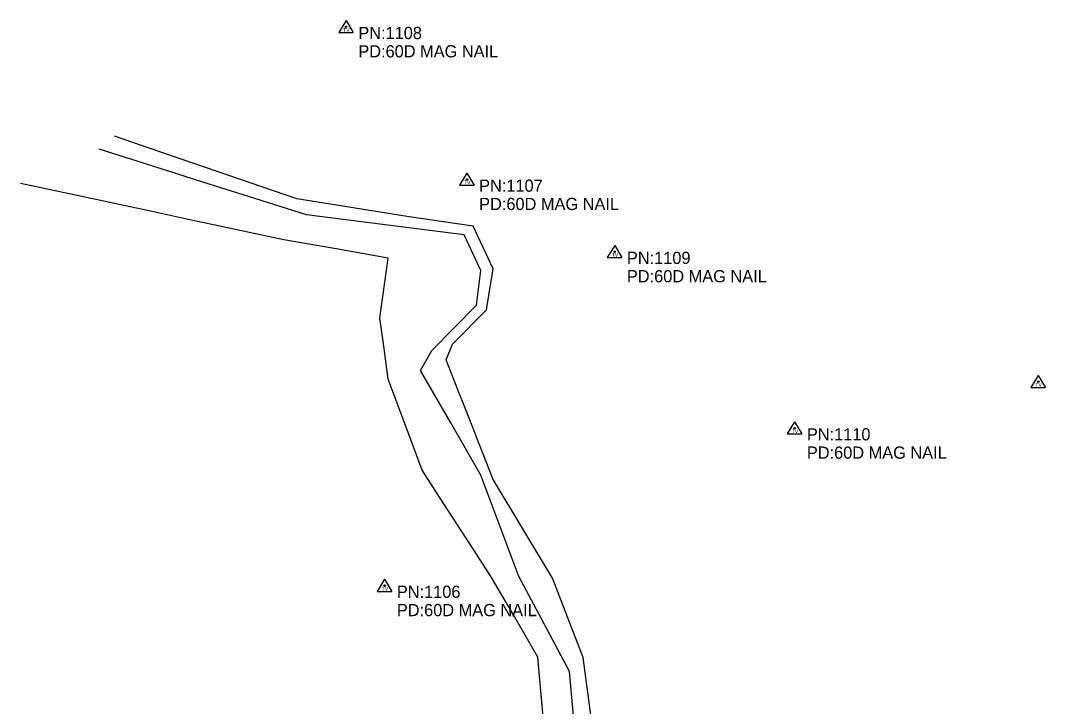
# Model space of a CAD drawing. Extents: x 1568433 to 1572450, y 731863 to 733450.
# Drawn here: x 1570330.9 to 1570750.2, y 732343.4 to 732624.2 of the extents above; entities that cross this region are included whole.
import ezdxf

# ---------------------------------------------------------------- set-up
doc = ezdxf.new("R2010")
doc.units = 0
for name, color, linetype in [('S_SECONDARY_CTL', 7, 'Continuous'), ('S_SECONDARY_CTL_ANNOT', 7, 'Continuous'), ('S_STREAM', 7, 'Continuous')]:
    doc.layers.add(name, color=color, linetype=linetype)

msp = doc.modelspace()

# ---------------------------------------------------------------- linework, layer by layer
at = {"layer": 'S_SECONDARY_CTL'}
for p, q in [((1570464.12, 732624.24), (1570461.11, 732619.28)), ((1570464.12, 732624.24), (1570467.06, 732619.28)), ((1570461.11, 732619.28), (1570467.06, 732619.28)), ((1570513.54, 732561.75), (1570510.53, 732556.79)), ((1570513.54, 732561.75), (1570516.49, 732556.79)), ((1570510.53, 732556.79), (1570516.49, 732556.79)), ((1570573.99, 732532.17), (1570570.98, 732527.22)), ((1570573.99, 732532.17), (1570576.94, 732527.22)), ((1570570.98, 732527.22), (1570576.94, 732527.22)), ((1570747.28, 732478.97), (1570744.27, 732474.02)), ((1570747.28, 732478.97), (1570750.23, 732474.02)), ((1570744.27, 732474.02), (1570750.23, 732474.02)), ((1570647.61, 732459.96), (1570644.6, 732455.01)), ((1570647.61, 732459.96), (1570650.56, 732455.01)), ((1570644.6, 732455.01), (1570650.56, 732455.01)), ((1570479.88, 732395.5), (1570476.87, 732390.54)), ((1570479.88, 732395.5), (1570482.83, 732390.54)), ((1570476.87, 732390.54), (1570482.83, 732390.54))]:
    msp.add_line(p, q, dxfattribs=at)
for centre, radius in [((1570464.12, 732621.63), 0.311), ((1570464.12, 732621.63), 0.183), ((1570464.12, 732621.63), 0.103), ((1570513.54, 732559.14), 0.311), ((1570513.54, 732559.14), 0.183), ((1570513.54, 732559.14), 0.103), ((1570573.99, 732529.56), 0.311), ((1570573.99, 732529.56), 0.183), ((1570573.99, 732529.56), 0.103), ((1570747.28, 732476.36), 0.311), ((1570747.28, 732476.36), 0.183), ((1570747.28, 732476.36), 0.103), ((1570647.61, 732457.35), 0.311), ((1570647.61, 732457.35), 0.183), ((1570647.61, 732457.35), 0.103), ((1570479.88, 732392.88), 0.311), ((1570479.88, 732392.88), 0.183), ((1570479.88, 732392.88), 0.103)]:
    msp.add_circle(centre, radius, dxfattribs=at)
at = {"layer": 'S_STREAM'}
for points in [[(1570564.95, 732334.87), (1570563.05, 732349.18), (1570561.16, 732363.48), (1570554.84, 732379.73), (1570548.51, 732395.97), (1570536.42, 732416.12), (1570524.32, 732436.28), (1570519.49, 732448.54), (1570514.67, 732460.81), (1570509.85, 732473.07), (1570505.02, 732485.33), (1570507.62, 732491.73), (1570521.54, 732505.77), (1570524.26, 732522.58), (1570516.08, 732540.07), (1570503.01, 732541.98), (1570489.94, 732543.9), (1570466.95, 732547.6), (1570443.95, 732551.29), (1570425.29, 732557.69), (1570406.63, 732564.08), (1570387.97, 732570.48), (1570369.31, 732576.88)], [(1570557.68, 732333.41), (1570555.51, 732357.8), (1570545.12, 732377.22), (1570534.73, 732396.65), (1570526.99, 732417.4), (1570519.24, 732438.15), (1570506.91, 732459.56), (1570494.58, 732480.97), (1570499.22, 732489.12), (1570508.32, 732498.42), (1570517.42, 732507.73), (1570519.2, 732521.86), (1570512.35, 732536.44), (1570496.25, 732538.5), (1570480.14, 732540.56), (1570464.04, 732542.62), (1570447.94, 732544.68), (1570447.94, 732544.69), (1570426.73, 732551.4), (1570405.51, 732558.11), (1570384.3, 732564.82), (1570363.08, 732571.54)], [(1570545.02, 732336.22), (1570543.82, 732349.9), (1570542.62, 732363.59), (1570533.09, 732379.92), (1570523.57, 732396.24), (1570516.49, 732407.22), (1570509.41, 732418.19), (1570502.32, 732429.17), (1570495.24, 732440.14), (1570488.3, 732458.81), (1570481.36, 732477.48), (1570479.63, 732489.94), (1570477.91, 732502.4), (1570481.38, 732527.01), (1570460.02, 732530.72), (1570438.66, 732534.43), (1570425.2, 732537.32), (1570411.73, 732540.21), (1570398.26, 732543.1), (1570384.79, 732545.99), (1570371.32, 732548.89), (1570357.86, 732551.78), (1570344.39, 732554.67), (1570330.92, 732557.56)]]:
    msp.add_lwpolyline(points, dxfattribs=at)

# ---------------------------------------------------------------- texts
at = {"layer": 'S_SECONDARY_CTL'}
for p in [(1570462.91, 732619.62), (1570512.34, 732557.13), (1570572.79, 732527.55), (1570746.08, 732474.35), (1570646.41, 732455.34), (1570478.68, 732390.87)]:
    msp.add_text('TV', height=1.5, dxfattribs=at).set_placement(p)
at = {"layer": 'S_SECONDARY_CTL_ANNOT'}
for s, p in [('PN:1108', (1570469.12, 732616.63)), ('PD:60D MAG NAIL', (1570469.12, 732609.13)), ('PN:1107', (1570518.54, 732554.14)), ('PD:60D MAG NAIL', (1570518.54, 732546.64)), ('PN:1109', (1570578.99, 732524.56)), ('PD:60D MAG NAIL', (1570578.99, 732517.06)), ('PN:1110', (1570652.61, 732452.35)), ('PD:60D MAG NAIL', (1570652.61, 732444.85)), ('PN:1106', (1570484.88, 732387.89)), ('PD:60D MAG NAIL', (1570484.88, 732380.39))]:
    msp.add_text(s, height=5, dxfattribs=at).set_placement(p)

doc.saveas('drawing.dxf')
